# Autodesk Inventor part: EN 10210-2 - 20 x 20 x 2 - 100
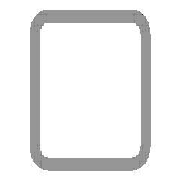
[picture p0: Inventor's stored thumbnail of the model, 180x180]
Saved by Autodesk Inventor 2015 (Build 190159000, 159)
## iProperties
Created: 2015-05
Part Number: EN 10210-2 - 20 x 20 x 2 - 100
Material: Steel, Mild
Description: Tube
Document SubType Name: Modeling
Standard: DIN
Designer: TREINA6
Standard Revision: 1997
Standards Organization: DIN
Language: en-US
Size Designation: 20 x 20 x 2
Categories: <MemberInstance><Categories><Category DisplayName="Structural Shapes" InternalName="089c4875-fa83-4c05-b084-43b9cc11f5ed" Mnemonic="GRDR"><CategoryParameter Dis
Stock Number: 20 x 20 x 2
Density: 7.85 g/cm^3
Appearance: Semi-Polished
_CCFamilyMember: 1
_CCFamilyDisplayName: DIN EN 10210-2 (Square) - Tube
_FrameMemberDoc: Frame Member File
_Version: 15.0.0
_GetPNFromCC: 1
IsCustomPart: 1
Author: TREINA6
G_L: 100,000 mm
G_W: 20,000 mm
G_H: 20,000 mm
+C6974BCF-1B59-4DE7-8265-DB1344D5870A+CUTDETAIL1: Miter 45,00 deg
+6D4B1D60-CFD2-41F1-9A60-DCD532D67BE1+CUTDETAIL2: Miter 45,00 deg
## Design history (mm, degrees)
node "Start plane"
node "End plane"
sketch "Sketch"
  geometry: L1 (-10, -7)-(-10, 7); L2 (-7, 10)-(7, 10); L3 (10, 7)-(10, -7); L4 (7, -10)-(-7, -10); L5 (-7, 8)-(7, 8); L6 (8, 7)-(8, -7); L7 (7, -8)-(-7, -8); L8 (-8, -7)-(-8, 7); L9 (0, 14.87)-(0, -14.87) reference; L10 (-14.87, 0)-(14.87, 0) reference; A1 r 3 centre (-7, -7) between (-10, -7) and (-7, -10); A2 r 3 centre (-7, 7) between (-7, 10) and (-10, 7); A3 r 3 centre (7, 7) between (10, 7) and (7, 10); A4 r 3 centre (7, -7) between (7, -10) and (10, -7); A5 r 1 centre (-7, 7) between (-7, 8) and (-8, 7); A6 r 1 centre (7, 7) between (8, 7) and (7, 8); A7 r 1 centre (7, -7) between (7, -8) and (8, -7); A8 r 1 centre (-7, -7) between (-8, -7) and (-7, -8)
  constraints: 16 end point, 16 point on circle, 8 centre point, 8 tangent, 4 parallel, 3 equal radius, 2 perpendicular, 7 other
  dimensions: "d7" = 3 radius of A1 (= G_IR); "d10" = 20 distance between parallel lines of L2 L4 (= G_H); "d11" = 20 distance between parallel lines of L1 L3 (= G_W); "d12" = 2 distance between parallel lines of L3 L6 (= G_T); "d15" = 10 distance between parallel lines of L2 L10 (= 0.5 x d10); "d16" = 10 distance between parallel lines of L9 L3 (= 0.5 x d11)
extrude "Body" new body sketch "Sketch" stored distance "d3" = 100 (= G_L); taper "d4" = 0 deg
node "Driven Length"
  sketch "Sketch3"
    geometry: L1 (0, 0)-(10, 0) reference
    constraints: 2 end point, 1 horizontal
  workplane "Work Plane3"
  sketch "Sketch4"
    geometry: L1 (-2, 0)-(12, 0) reference; L2 (-2, 100)-(12, 100) reference
    dimensions: "d18" = 100 distance between parallel lines of L1 L2 (derived)
workplane "Work Plane4"
split "Split1"
workplane "Work Plane5"
split "Split2"
body "Solid1"
other parameters: "G_W" = 20 [user parameter; used in 1 equation term], "G_H" = 20 [user parameter; used in 1 equation term], "G_T" = 2 [user parameter; used in 1 equation term], "G_IR" = 3 [user parameter; used in 1 equation term], "G_L" = 100 (= d18) [user parameter; used in 1 equation term], "G_OFFSET_START" = 0 [user parameter; used in 1 equation term], "G_OFFSET_END" = 0 [user parameter; used in 1 equation term], "d13" = 0 (computed from G_OFFSET_START), "d17" = 90 deg
